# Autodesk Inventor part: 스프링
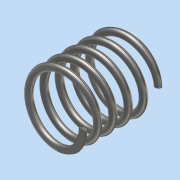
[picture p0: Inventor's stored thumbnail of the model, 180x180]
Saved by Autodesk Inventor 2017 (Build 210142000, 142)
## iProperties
Part Number: 스프링
Material: 스테인레스 스틸
Document SubType Name: Modeling
Designer: MRC
Density: 8 g/cm^3
Appearance: 반연마
Mass: 6.97832 g
Surface Area: 17.713 cm^2
Volume: 0.872289 cm^3
Author: MRC
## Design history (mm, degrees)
sketch "스케치1"
  geometry: L1 (0, 0)-(0, 22.5); L2 (0, 22.5)-(9, 22.5); L3 (0, 0)-(9, 0); C1 r 1 at (9, 0); 1 further point
  constraints: 6 end point, 2 coincident, 2 horizontal, 1 centre point, 1 vertical
  dimensions: "d0" = 22.5 distance of L1.start L1.end (derived); "d1" = 9 distance of L1.end L2.end; "d2" = 9 distance of L1.start L3.end; "d3" = 2 diameter of C1
feature "코일1" sketch "스케치1" pitch "d4" = 10; turns "d6" = 5; dims "d5" = 22.5 (= d0), "d7" = 0, angle "d8" = 90 deg, angle "d9" = 90 deg, "d10" = 0, "d11" = 0
sketch "스케치2"
  geometry: L1 (22.5, 15)-(0, 15); L2 (0, 15)-(0, -15); L3 (0, -15)-(22.5, -15); L4 (22.5, -15)-(22.5, 15); 2 further points
  constraints: 8 end point, 2 parallel, 1 coincident, 1 horizontal, 1 midpoint, 1 perpendicular
  dimensions: "d12" = 22.5 distance of L2.end L3.end (= d0); "d13" = 30 distance of L3.end L1.start
extrude "돌출1" sketch "스케치2" stored distance "d14" = 0; taper "d15" = 0 deg
node "솔리드1"
